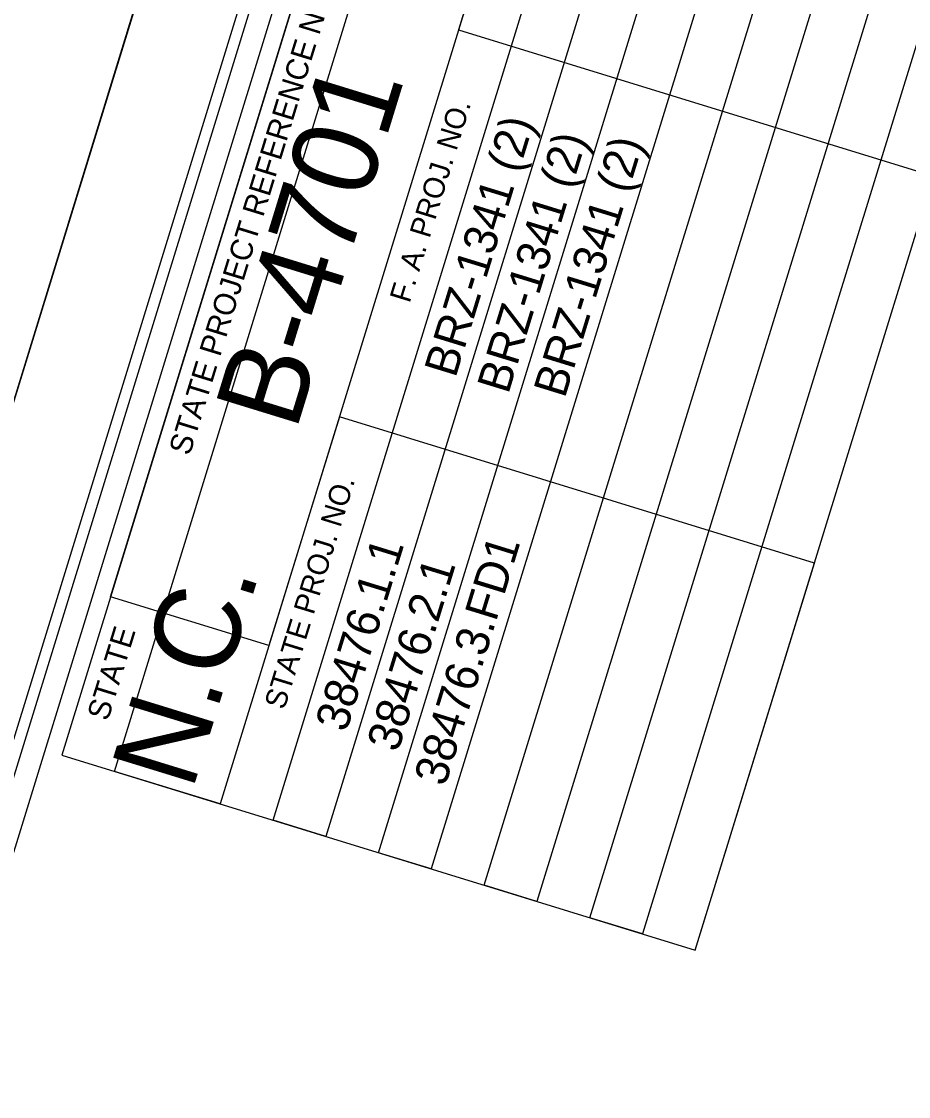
# Model space of a CAD drawing. Extents: x 1347947 to 1350662, y 1027710 to 1030532.
# Drawn here: x 1348377.3 to 1348578, y 1029792.5 to 1030035.7 of the extents above; entities that cross this region are included whole.
import ezdxf

# ---------------------------------------------------------------- set-up
doc = ezdxf.new("R2010")
doc.units = 0
for name, color, linetype in [('Sheet Cutting Line CELL', 7, 'Continuous'), ('Sheet Data Field CELL', 7, 'Continuous'), ('Sheet Plot Border Inside CELL', 7, 'Continuous'), ('Sheet Plot Border Outside CELL', 7, 'Continuous'), ('Sheet Title CELL', 7, 'Continuous')]:
    doc.layers.add(name, color=color, linetype=linetype)

msp = doc.modelspace()

# ---------------------------------------------------------------- linework, layer by layer
at = {"layer": 'Sheet Cutting Line CELL'}
msp.add_line((1347946.88, 1028557.97), (1348442.51, 1030167.38), dxfattribs=at)
at = {"layer": 'Sheet Plot Border Inside CELL'}
msp.add_lwpolyline([(1348980.53, 1028253.25), (1349471, 1029845.94), (1348462.64, 1030156.47), (1347972.16, 1028563.78)], close=True, dxfattribs=at)
at = {"layer": 'Sheet Plot Border Outside CELL'}
msp.add_lwpolyline([(1348442.51, 1030167.38), (1347946.88, 1028557.97), (1348998.14, 1028234.22), (1349493.77, 1029843.63)], close=True, dxfattribs=at)
at = {"layer": 'Sheet Title CELL'}
for points in [[(1348458.46, 1030134.23), (1348022.85, 1028719.76)], [(1348467.34, 1030132.53), (1348386.41, 1029869.7), (1348529.76, 1029825.56), (1348556.74, 1029913.15), (1348449.22, 1029946.26), (1348433.29, 1029894.51), (1348397.44, 1029905.55), (1348445.28, 1030060.86)], [(1348461.76, 1030127.97), (1348043.83, 1028770.87)], [(1348503.18, 1030121.49), (1348422.24, 1029858.67), (1348398.35, 1029866.03), (1348479.28, 1030128.85)], [(1348527.08, 1030114.13), (1348446.14, 1029851.31), (1348434.2, 1029854.99), (1348515.13, 1030117.81)], [(1348550.96, 1030106.77), (1348470.02, 1029843.95), (1348458.09, 1029847.63), (1348539.01, 1030110.45)], [(1348574.87, 1030099.41), (1348493.93, 1029836.61), (1348481.97, 1029840.28), (1348562.91, 1030103.1)], [(1348598.76, 1030092.05), (1348517.81, 1029829.24), (1348505.87, 1029832.91), (1348586.81, 1030095.73)], [(1348481.1, 1030049.81), (1348476.19, 1030033.85), (1348583.7, 1030000.74), (1348610.69, 1030088.38)], [(1348529.76, 1029825.56), (1348610.69, 1030088.38)]]:
    msp.add_lwpolyline(points, dxfattribs=at)

# ---------------------------------------------------------------- texts
at = {"layer": 'Sheet Data Field CELL'}
for s, p in [('BRZ-1341 (2)  ', (1348475.47, 1029954.87)), ('BRZ-1341 (2)  ', (1348487.42, 1029951.19)), ('BRZ-1341 (2)', (1348500.2, 1029950.26)), ('38476.3.FD1', (1348473.14, 1029862.4)), ('38476.1.1 ', (1348450.78, 1029874.68)), ('38476.2.1 ', (1348462.46, 1029870.15))]:
    msp.add_text(s, height=7.5, rotation=72.8834, dxfattribs=at).set_placement(p)
at = {"layer": 'Sheet Title CELL'}
for s, height, p in [('STATE PROJECT REFERENCE NO.', 4.9998, (1348415.33, 1029937.29)), ('B-4701', 19.35, (1348439.36, 1029942.76)), ('F. A. PROJ. NO.', 4.8, (1348465.09, 1029971.82)), ('STATE PROJ. NO.', 4.8, (1348436.75, 1029879.79)), ('N.C.', 19.35, (1348415.91, 1029861.4)), ('STATE', 5, (1348396.82, 1029877.22))]:
    msp.add_text(s, height=height, rotation=72.8834, dxfattribs=at).set_placement(p)

doc.saveas('drawing.dxf')
